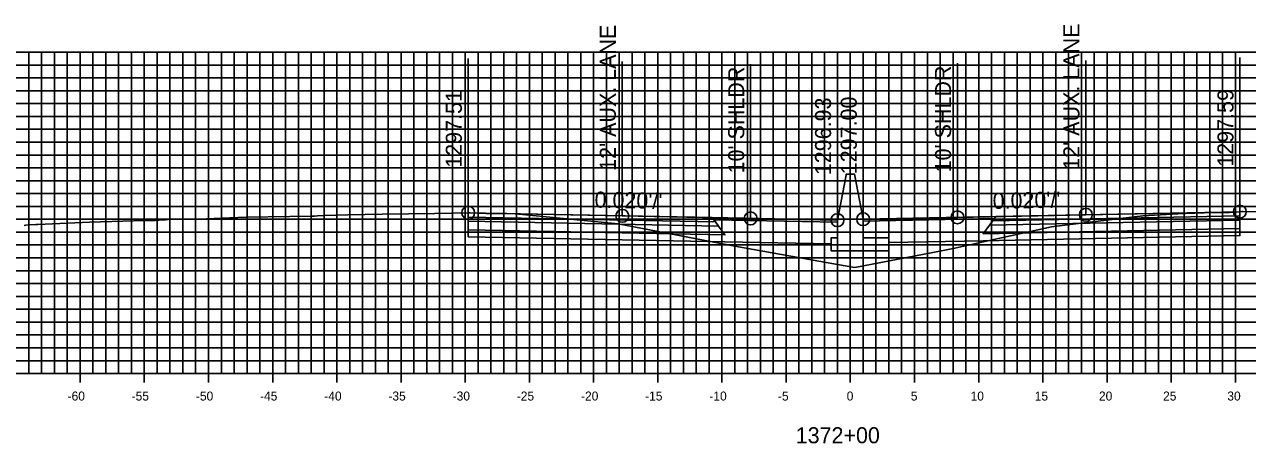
# Model space of a CAD drawing. Extents: x 674939 to 678919, y 750652 to 765176.
# Drawn here: x 678674.2 to 678769.5, y 754667.1 to 754699.7 of the extents above; entities that cross this region are included whole.
import ezdxf

# ---------------------------------------------------------------- set-up
doc = ezdxf.new("R2010")
doc.units = 0
for name, color, linetype in [('Level 10', 7, 'Continuous'), ('Level 17', 7, 'Continuous'), ('Level 18', 7, 'Continuous'), ('Level 19', 7, 'Continuous'), ('Level 20', 7, 'Continuous'), ('Level 22', 7, 'Continuous'), ('Level 23', 7, 'Continuous'), ('Level 4', 7, 'Continuous'), ('Level 8', 7, 'Continuous'), ('Level 9', 7, 'Continuous')]:
    doc.layers.add(name, color=color, linetype=linetype)

msp = doc.modelspace()

# ---------------------------------------------------------------- linework, layer by layer
at = {"layer": 'Level 10'}
msp.add_lwpolyline([(678674.168, 754684.055), (678674.31, 754684.082), (678674.545, 754684.113), (678675.094, 754684.138), (678675.25, 754684.148), (678679.263, 754684.32), (678681.851, 754684.41), (678683.553, 754684.445), (678684.024, 754684.45), (678684.389, 754684.456), (678684.7, 754684.479), (678685.174, 754684.514), (678685.308, 754684.523), (678685.389, 754684.529), (678686.969, 754684.561), (678688.381, 754684.597), (678690.204, 754684.67), (678691.46, 754684.708), (678694.862, 754684.771), (678696.511, 754684.799), (678696.667, 754684.795), (678696.789, 754684.786), (678697.024, 754684.811), (678697.511, 754684.853), (678699.396, 754684.891), (678702.068, 754684.938), (678706.178, 754685.012), (678708.768, 754685.059), (678708.772, 754685.059), (678708.91, 754685.062), (678709.517, 754685.032), (678710.146, 754685.011), (678710.997, 754685.008), (678711.232, 754685.012), (678711.783, 754684.994), (678712.435, 754684.98), (678712.459, 754684.982), (678720.183, 754684.219), (678720.38, 754684.199), (678720.449, 754684.186), (678729.531, 754682.453), (678737.541, 754681.039), (678738.894, 754680.807), (678745.635, 754682.106), (678746.664, 754682.303), (678747.853, 754682.561), (678750.999, 754683.255), (678754.209, 754683.964), (678755.449, 754684.109), (678761.309, 754684.83), (678764.502, 754685.002), (678764.651, 754685.012), (678764.67, 754685.013), (678766.8, 754685.089), (678766.871, 754685.091), (678768.032, 754685.087), (678768.065, 754685.088), (678768.867, 754685.141), (678768.881, 754685.142), (678769.046, 754685.153), (678769.058, 754685.154), (678769.136, 754685.153), (678772.233, 754685.098)], dxfattribs=at)
at = {"layer": 'Level 17'}
for points in [[(678738.203, 754687.983), (678737.533, 754684.483)], [(678738.863, 754688.055), (678738.863, 754688.055), (678738.203, 754688.055), (678738.203, 754687.983)], [(678738.863, 754688.055), (678739.533, 754684.555)], [(678737.533, 754684.483), (678737.533, 754683.108), (678737.033, 754683.108), (678737.033, 754682.108), (678741.533, 754682.108), (678741.533, 754683.108), (678739.533, 754683.108), (678739.533, 754684.555)]]:
    msp.add_lwpolyline(points, dxfattribs=at)
at = {"layer": 'Level 18'}
for points in [[(678737.533, 754684.483), (678730.768, 754684.619), (678720.768, 754684.819), (678708.768, 754685.059)], [(678768.881, 754685.142), (678756.881, 754684.902), (678746.881, 754684.702), (678739.533, 754684.555)]]:
    msp.add_lwpolyline(points, dxfattribs=at)
for points in [[(678708.768, 754685.059), (678708.768, 754684.729), (678728.018, 754684.344), (678727.768, 754684.679)], [(678768.881, 754685.142), (678768.881, 754684.812), (678749.631, 754684.427), (678749.881, 754684.762)], [(678727.768, 754684.679), (678737.533, 754684.483), (678737.537, 754684.326), (678727.888, 754684.519)], [(678749.762, 754684.602), (678739.533, 754684.397), (678739.533, 754684.555), (678749.881, 754684.762)]]:
    msp.add_lwpolyline(points, close=True, dxfattribs=at)
at = {"layer": 'Level 19'}
for points in [[(678708.768, 754684.729), (678708.768, 754684.399), (678728.268, 754684.009), (678728.018, 754684.344)], [(678708.768, 754684.399), (678708.768, 754683.739), (678728.768, 754683.339), (678728.268, 754684.009)], [(678768.881, 754684.482), (678768.881, 754683.822), (678748.881, 754683.422), (678749.381, 754684.092)], [(678768.881, 754684.812), (678768.881, 754684.482), (678749.381, 754684.092), (678749.631, 754684.427)]]:
    msp.add_lwpolyline(points, close=True, dxfattribs=at)
for points in [[(678708.768, 754683.739), (678708.768, 754683.199), (678728.768, 754682.799), (678737.033, 754682.633)], [(678768.881, 754683.822), (678768.881, 754683.282), (678748.881, 754682.882), (678741.533, 754682.735)]]:
    msp.add_lwpolyline(points, dxfattribs=at)
at = {"layer": 'Level 20'}
for p, q in [((678638.533, 754697.551), (678838.533, 754697.551)), ((678674.533, 754672.551), (678674.533, 754697.551)), ((678675.533, 754672.551), (678675.533, 754697.551)), ((678676.533, 754672.551), (678676.533, 754697.551)), ((678677.533, 754672.551), (678677.533, 754697.551)), ((678678.533, 754672.551), (678678.533, 754697.551)), ((678679.533, 754672.551), (678679.533, 754697.551)), ((678680.533, 754672.551), (678680.533, 754697.551)), ((678681.533, 754672.551), (678681.533, 754697.551)), ((678682.533, 754672.551), (678682.533, 754697.551)), ((678683.533, 754672.551), (678683.533, 754697.551)), ((678684.533, 754672.551), (678684.533, 754697.551)), ((678685.533, 754672.551), (678685.533, 754697.551)), ((678686.533, 754672.551), (678686.533, 754697.551)), ((678687.533, 754672.551), (678687.533, 754697.551)), ((678688.533, 754672.551), (678688.533, 754697.551)), ((678689.533, 754672.551), (678689.533, 754697.551)), ((678690.533, 754672.551), (678690.533, 754697.551)), ((678691.533, 754672.551), (678691.533, 754697.551)), ((678692.533, 754672.551), (678692.533, 754697.551)), ((678693.533, 754672.551), (678693.533, 754697.551)), ((678694.533, 754672.551), (678694.533, 754697.551)), ((678695.533, 754672.551), (678695.533, 754697.551)), ((678696.533, 754672.551), (678696.533, 754697.551)), ((678697.533, 754672.551), (678697.533, 754697.551)), ((678698.533, 754672.551), (678698.533, 754697.551)), ((678699.533, 754672.551), (678699.533, 754697.551)), ((678700.533, 754672.551), (678700.533, 754697.551)), ((678701.533, 754672.551), (678701.533, 754697.551)), ((678702.533, 754672.551), (678702.533, 754697.551)), ((678703.533, 754672.551), (678703.533, 754697.551)), ((678704.533, 754672.551), (678704.533, 754697.551)), ((678705.533, 754672.551), (678705.533, 754697.551)), ((678706.533, 754672.551), (678706.533, 754697.551)), ((678707.533, 754672.551), (678707.533, 754697.551)), ((678708.533, 754672.551), (678708.533, 754697.551)), ((678709.533, 754672.551), (678709.533, 754697.551)), ((678710.533, 754672.551), (678710.533, 754697.551)), ((678711.533, 754672.551), (678711.533, 754697.551)), ((678712.533, 754672.551), (678712.533, 754697.551)), ((678713.533, 754672.551), (678713.533, 754697.551)), ((678714.533, 754672.551), (678714.533, 754697.551)), ((678715.533, 754672.551), (678715.533, 754697.551)), ((678716.533, 754672.551), (678716.533, 754697.551)), ((678717.533, 754672.551), (678717.533, 754697.551)), ((678718.533, 754672.551), (678718.533, 754697.551)), ((678719.533, 754672.551), (678719.533, 754697.551)), ((678720.533, 754672.551), (678720.533, 754697.551)), ((678721.533, 754672.551), (678721.533, 754697.551)), ((678722.533, 754672.551), (678722.533, 754697.551)), ((678723.533, 754672.551), (678723.533, 754697.551)), ((678724.533, 754672.551), (678724.533, 754697.551)), ((678725.533, 754672.551), (678725.533, 754697.551)), ((678726.533, 754672.551), (678726.533, 754697.551)), ((678727.533, 754672.551), (678727.533, 754697.551)), ((678728.533, 754672.551), (678728.533, 754697.551)), ((678729.533, 754672.551), (678729.533, 754697.551)), ((678730.533, 754672.551), (678730.533, 754697.551)), ((678731.533, 754672.551), (678731.533, 754697.551)), ((678732.533, 754672.551), (678732.533, 754697.551)), ((678733.533, 754672.551), (678733.533, 754697.551)), ((678734.533, 754672.551), (678734.533, 754697.551)), ((678735.533, 754672.551), (678735.533, 754697.551)), ((678736.533, 754672.551), (678736.533, 754697.551)), ((678737.533, 754672.551), (678737.533, 754697.551)), ((678738.533, 754672.551), (678738.533, 754697.551)), ((678739.533, 754672.551), (678739.533, 754697.551)), ((678740.533, 754672.551), (678740.533, 754697.551)), ((678741.533, 754672.551), (678741.533, 754697.551)), ((678742.533, 754672.551), (678742.533, 754697.551)), ((678743.533, 754672.551), (678743.533, 754697.551)), ((678744.533, 754672.551), (678744.533, 754697.551)), ((678745.533, 754672.551), (678745.533, 754697.551)), ((678746.533, 754672.551), (678746.533, 754697.551)), ((678747.533, 754672.551), (678747.533, 754697.551)), ((678748.533, 754672.551), (678748.533, 754697.551)), ((678749.533, 754672.551), (678749.533, 754697.551)), ((678750.533, 754672.551), (678750.533, 754697.551)), ((678751.533, 754672.551), (678751.533, 754697.551)), ((678752.533, 754672.551), (678752.533, 754697.551)), ((678753.533, 754672.551), (678753.533, 754697.551)), ((678754.533, 754672.551), (678754.533, 754697.551)), ((678755.533, 754672.551), (678755.533, 754697.551)), ((678756.533, 754672.551), (678756.533, 754697.551)), ((678757.533, 754672.551), (678757.533, 754697.551)), ((678758.533, 754672.551), (678758.533, 754697.551)), ((678759.533, 754672.551), (678759.533, 754697.551)), ((678760.533, 754672.551), (678760.533, 754697.551)), ((678761.533, 754672.551), (678761.533, 754697.551)), ((678762.533, 754672.551), (678762.533, 754697.551)), ((678763.533, 754672.551), (678763.533, 754697.551)), ((678764.533, 754672.551), (678764.533, 754697.551)), ((678765.533, 754672.551), (678765.533, 754697.551)), ((678766.533, 754672.551), (678766.533, 754697.551)), ((678767.533, 754672.551), (678767.533, 754697.551)), ((678768.533, 754672.551), (678768.533, 754697.551)), ((678638.533, 754696.551), (678838.533, 754696.551)), ((678638.533, 754695.551), (678838.533, 754695.551)), ((678638.533, 754694.551), (678838.533, 754694.551)), ((678638.533, 754693.551), (678838.533, 754693.551)), ((678638.533, 754692.551), (678838.533, 754692.551)), ((678638.533, 754691.551), (678838.533, 754691.551)), ((678638.533, 754690.551), (678838.533, 754690.551)), ((678638.533, 754689.551), (678838.533, 754689.551)), ((678638.533, 754688.551), (678838.533, 754688.551)), ((678638.533, 754687.551), (678838.533, 754687.551)), ((678638.533, 754686.551), (678838.533, 754686.551)), ((678638.533, 754685.551), (678838.533, 754685.551)), ((678638.533, 754684.551), (678838.533, 754684.551)), ((678638.533, 754683.551), (678838.533, 754683.551)), ((678638.533, 754682.551), (678838.533, 754682.551)), ((678638.533, 754681.551), (678838.533, 754681.551)), ((678638.533, 754680.551), (678838.533, 754680.551)), ((678638.533, 754679.551), (678838.533, 754679.551)), ((678638.533, 754678.551), (678838.533, 754678.551)), ((678638.533, 754677.551), (678838.533, 754677.551)), ((678638.533, 754676.551), (678838.533, 754676.551)), ((678638.533, 754675.551), (678838.533, 754675.551)), ((678638.533, 754674.551), (678838.533, 754674.551)), ((678638.533, 754673.551), (678838.533, 754673.551)), ((678638.533, 754672.551), (678838.533, 754672.551))]:
    msp.add_line(p, q, dxfattribs=at)
at = {"layer": 'Level 23'}
for p, q in [((678708.768, 754685.059), (678708.768, 754697.059)), ((678720.768, 754684.819), (678720.768, 754696.819)), ((678730.768, 754684.619), (678730.768, 754696.619)), ((678737.533, 754684.483), (678737.533, 754696.483)), ((678739.533, 754684.555), (678739.533, 754696.555)), ((678746.881, 754684.702), (678746.881, 754696.702)), ((678756.881, 754684.902), (678756.881, 754696.902)), ((678768.881, 754685.142), (678768.881, 754697.142))]:
    msp.add_line(p, q, dxfattribs=at)
at = {"layer": 'Level 4'}
for centre in [(678708.768, 754685.059), (678720.768, 754684.819), (678730.768, 754684.619), (678737.533, 754684.483), (678739.533, 754684.555), (678746.881, 754684.702), (678756.881, 754684.902), (678768.881, 754685.142)]:
    msp.add_circle(centre, 0.5, dxfattribs=at)
at = {"layer": 'Level 8'}
for p, q in [((678638.533, 754672.551), (678838.533, 754672.551)), ((678678.533, 754671.851), (678678.533, 754673.251)), ((678683.533, 754671.851), (678683.533, 754673.251)), ((678688.533, 754671.851), (678688.533, 754673.251)), ((678693.533, 754671.851), (678693.533, 754673.251)), ((678698.533, 754671.851), (678698.533, 754673.251)), ((678703.533, 754671.851), (678703.533, 754673.251)), ((678708.533, 754671.851), (678708.533, 754673.251)), ((678713.533, 754671.851), (678713.533, 754673.251)), ((678718.533, 754671.851), (678718.533, 754673.251)), ((678723.533, 754671.851), (678723.533, 754673.251)), ((678728.533, 754671.851), (678728.533, 754673.251)), ((678733.533, 754671.851), (678733.533, 754673.251)), ((678738.533, 754671.851), (678738.533, 754673.251)), ((678743.533, 754671.851), (678743.533, 754673.251)), ((678748.533, 754671.851), (678748.533, 754673.251)), ((678753.533, 754671.851), (678753.533, 754673.251)), ((678758.533, 754671.851), (678758.533, 754673.251)), ((678763.533, 754671.851), (678763.533, 754673.251)), ((678768.533, 754671.851), (678768.533, 754673.251))]:
    msp.add_line(p, q, dxfattribs=at)

# ---------------------------------------------------------------- texts
at = {"layer": 'Level 22'}
for rotation, p in [(1.14576, (678749.633, 754685.357)), (358.85424, (678718.601, 754685.462))]:
    msp.add_text("0.020'/'", height=1.25, rotation=rotation, dxfattribs=at).set_placement(p)
at = {"layer": 'Level 23'}
for s, p in [("12' AUX. LANE", (678720.268, 754688.319)), ("12' AUX. LANE", (678756.381, 754688.402)), ("10' SHLDR", (678730.268, 754688.119)), ("10' SHLDR", (678746.381, 754688.202)), ('1297.51', (678708.268, 754688.559)), ('1297.59', (678768.381, 754688.642)), ('1296.93', (678737.033, 754687.983)), ('1297.00', (678739.033, 754688.055))]:
    msp.add_text(s, height=1.25, rotation=90, dxfattribs=at).set_placement(p)
at = {"layer": 'Level 9'}
for s, height, p in [('-60', 0.7, (678677.552, 754670.451)), ('-55', 0.7, (678682.546, 754670.451)), ('-50', 0.7, (678687.552, 754670.451)), ('-45', 0.7, (678692.546, 754670.451)), ('-40', 0.7, (678697.552, 754670.451)), ('-35', 0.7, (678702.546, 754670.451)), ('-30', 0.7, (678707.552, 754670.451)), ('-25', 0.7, (678712.546, 754670.451)), ('-20', 0.7, (678717.552, 754670.451)), ('-15', 0.7, (678722.546, 754670.451)), ('-10', 0.7, (678727.552, 754670.451)), ('-5', 0.7, (678732.896, 754670.451)), ('0', 0.7, (678738.252, 754670.451)), ('5', 0.7, (678743.246, 754670.451)), ('10', 0.7, (678747.902, 754670.451)), ('15', 0.7, (678752.896, 754670.451)), ('20', 0.7, (678757.902, 754670.451)), ('25', 0.7, (678762.896, 754670.451)), ('30', 0.7, (678767.902, 754670.451)), ('1372+00', 1.25, (678734.281, 754667.126))]:
    msp.add_text(s, height=height, dxfattribs=at).set_placement(p)

doc.saveas('drawing.dxf')
